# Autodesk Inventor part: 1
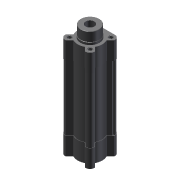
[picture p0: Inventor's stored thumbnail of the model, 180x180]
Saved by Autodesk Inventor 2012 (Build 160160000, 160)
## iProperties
Company: CAD-Verlag
Created: 2004-09
Part Number: 1
Document SubType Name: Modeling
Designer: Greiling
Manufacturer: Standard
Standards Organization: Custom
Density: 1 g/cm^3
Checked By: Jürgen Kronas
Stock Number: 10-10010
Material: Standard
Übersetzungsnorm: STEP AP203
Dateiname: s:/PartAssembly/iodir/wkb1973826_no0//0//532740_DNCB_40_80_PPV_A.stp
Postprozessor: Build: 096e, Release: 9 RTM - Date: Thu 06/17/2004
Gesendete Einheiten: MILLIMETERS
Unbestimmtheit: 1.0000000000000002e-06
Author: Juergen Kronas
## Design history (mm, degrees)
node "Basis1"
node "Volumenkörper1"
node "Volumenkörpern"
node "Oberflächenkörpern"
